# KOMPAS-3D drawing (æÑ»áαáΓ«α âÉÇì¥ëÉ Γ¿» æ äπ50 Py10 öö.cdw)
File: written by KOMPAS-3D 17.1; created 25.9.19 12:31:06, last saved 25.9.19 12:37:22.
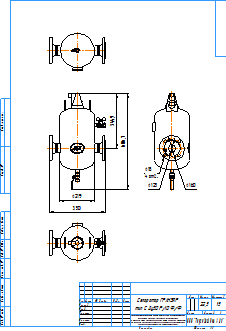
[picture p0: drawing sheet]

Sheet 1: A3, portrait

Title block, sheet 1: name: Сепаратор ГРАНЭЙР / тип С Ду50 Py10 Ф/Ф; material: Сталь 20  ГОСТ 1050-2013; mass: 22,5; sheets: 1; sheet format: A3; stored path: \\adlc.lan\data\АДЛ_ПКД\3D-модели\ADL production\Сепараторы воздуха ГРАНЭЙР\Гранэйр тип С\KOMPAS 2D\Сепаратор ГРАНЭЙР тип С Ду50 Py10 ФФ.cdw

Views: Вид 1, Проекционный вид 2, Проекционный вид 3, Проекционный вид 4
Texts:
  kka
  adl
  Рама для чертежей
  Лит-Масса-Масштаб
  Материал-Предприятие
  Масштаб
  Изм.
  Лист
  № докум.
  Подп.
  Дата
  Лит.
  Разраб.
  Пров.
  Т.контр.
  Листов
  Внимание! Данный продукт является объектом авторского права ООО «Торговый Дом АДЛ».
  Запрещается изменение, копирование, распространение
  (в том числе путем копирования на другие сайты и ресурсы в Интернете)
  или любое иное использование информации и объектов без предварительного
  согласия правообладателя (ООО «Торговый Дом АДЛ»).
  Н.контр.
  Утв.
  ООО "Торговый дом АДЛ"
  Изменение
  Номер документа
  Подпись
  Обозначение документа
  Наименование изделия
  Масса изделия по ГОСТ 2.109-73
  Порядковый номер листа
  Общее количество листов в документе
  Характер работы, выполненной лицом, подписавшим документ
  Наименование или индекс предприятия, выпускающего документ
  Инв. № подл.
  Подп. и дата
  Взам. инв. №
  Инв. № дубл.
  Инвентарный номер подлинника по ГОСТ 2.501-68
  Подпись принявшего подлинник в отдел технической документации
  Инвентарный номер подлинника, взамен которого выпущен данный подлинник
  Инвентарный номер дубликата по ГОСТ 2.502-68
  Подпись принявшего дубликат в отдел технической документации
  Справ. №
  Перв. примен.
  Обозначение документа, взамен или на основании которого выпущен данный документ
  Обозначение документа, в котором впервые записан данный документ
  Подпись лица, копировавшего чертеж
  Обозначение формата листа
  !Рама для чертежа
Dimensions and other numbers on the sheet: 350; 219; 344,9; 606,7; 125; 18; 4 отв.; 160; 1:5; 1; 22,5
